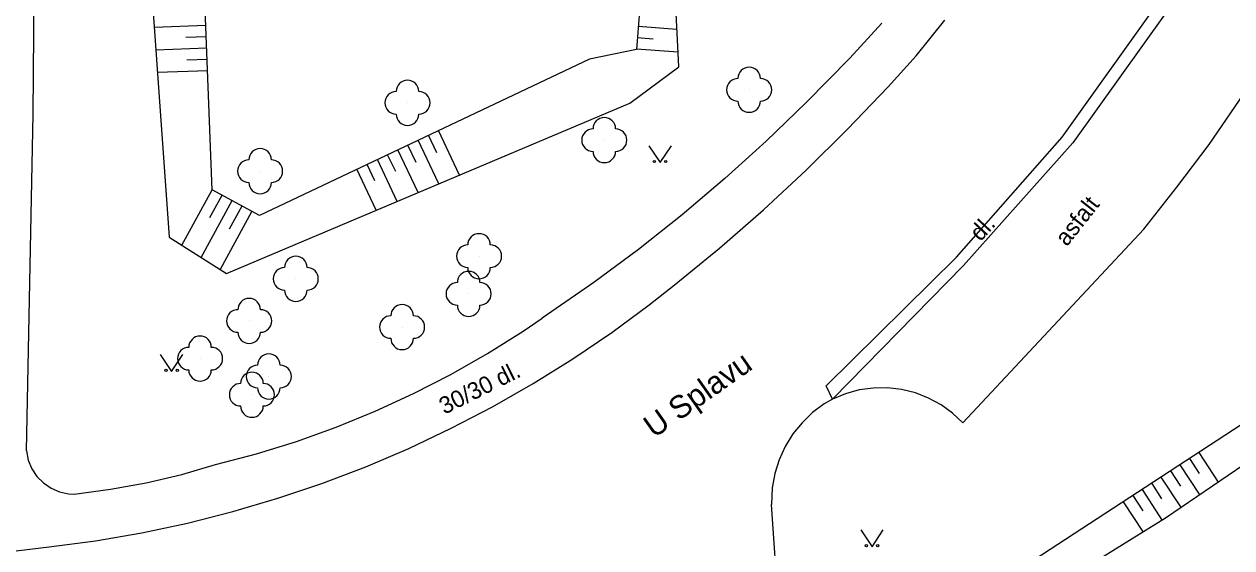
# Model space of a CAD drawing. Extents: x -584400 to -581602, y -1210894 to -1208793.
# Drawn here: x -583030.8 to -582977.3, y -1210509.9 to -1210486.7 of the extents above; entities that cross this region are included whole.
import ezdxf

# ---------------------------------------------------------------- set-up
doc = ezdxf.new("R2010")
doc.units = 0
for name, color, linetype in [('NÁZVY_ULIC_TOK_SMĚR', 7, 'Continuous'), ('POMOC_POPIS', 7, 'Continuous'), ('ROZHRANÍ_PLOCH', 7, 'Continuous'), ('VÝŠKOPIS', 7, 'Continuous'), ('ZELEŇ', 7, 'Continuous'), ('ZN_DOPLŇKOVÉ', 7, 'Continuous'), ('ZN_KULTUR', 7, 'Continuous')]:
    doc.layers.add(name, color=color, linetype=linetype)

msp = doc.modelspace()

# ---------------------------------------------------------------- linework, layer by layer
at = {"layer": 'ROZHRANÍ_PLOCH'}
for points in [[(-582994.96, -1210503.31), (-582995.24, -1210502.72), (-582989.47, -1210497.01), (-582984.79, -1210491.69), (-582980.68, -1210485.94), (-582976.77, -1210479.26), (-582974.08, -1210472.67), (-582971.69, -1210464.31), (-582970.39, -1210456.48), (-582969.87, -1210447.15), (-582969.4, -1210447.87)], [(-582969.4, -1210447.87), (-582969.86, -1210456.52), (-582971.17, -1210464.44), (-582973.64, -1210472.89), (-582976.31, -1210479.47), (-582980.23, -1210486.22), (-582984.31, -1210491.94), (-582989.16, -1210497.38), (-582994.96, -1210503.31)], [(-583030.67, -1210505.6), (-583030.37, -1210490.67), (-583030.19, -1210469.05), (-583024.56, -1210469.18)], [(-582989.19, -1210504.36), (-582981.17, -1210495.77), (-582979.7, -1210493.91), (-582978.28, -1210492.01), (-582976.93, -1210490.05), (-582975.65, -1210488.06), (-582974.43, -1210486.02), (-582973.28, -1210483.95), (-582972.21, -1210481.83), (-582971.2, -1210479.68), (-582970.27, -1210477.5), (-582969.42, -1210475.29), (-582968.42, -1210472.37)], [(-583032.48, -1210510.2), (-583029.66, -1210509.86), (-583027.61, -1210509.59), (-583025.56, -1210509.23), (-583023.54, -1210508.8), (-583021.53, -1210508.29), (-583019.54, -1210507.7), (-583017.58, -1210507.04), (-583015.64, -1210506.3), (-583013.73, -1210505.49), (-583011.86, -1210504.6), (-583010.02, -1210503.64), (-583008.22, -1210502.61), (-583006.46, -1210501.52), (-583004.74, -1210500.35), (-583003.08, -1210499.13), (-583001.98, -1210498.26), (-582999.97, -1210496.62), (-582998.02, -1210494.92), (-582996.13, -1210493.16), (-582994.29, -1210491.34), (-582992.5, -1210489.46), (-582991.26, -1210488.08), (-582989.98, -1210486.51)], [(-582992.77, -1210486.63), (-582994.2, -1210488.19), (-582996.13, -1210490.16), (-582997.9, -1210491.87), (-582999.73, -1210493.53), (-583001.62, -1210495.13), (-583003.55, -1210496.67), (-583005.53, -1210498.14), (-583007.82, -1210499.72)], [(-583030.67, -1210505.6), (-583030.59, -1210506.01), (-583030.43, -1210506.39), (-583030.21, -1210506.73), (-583029.92, -1210507.02), (-583029.58, -1210507.26), (-583029.2, -1210507.42), (-583028.8, -1210507.5), (-583028.55, -1210507.52), (-583026.95, -1210507.3), (-583025.36, -1210507.01), (-583023.79, -1210506.64), (-583022.29, -1210506.21), (-583020.48, -1210505.73), (-583018.7, -1210505.18), (-583016.95, -1210504.55), (-583015.22, -1210503.84), (-583013.53, -1210503.06), (-583011.87, -1210502.21), (-583010.25, -1210501.28), (-583008.67, -1210500.29), (-583007.82, -1210499.72)], [(-582989.19, -1210504.36), (-582989.64, -1210503.93), (-582990.15, -1210503.56), (-582990.71, -1210503.26), (-582991.29, -1210503.03), (-582991.9, -1210502.88), (-582992.53, -1210502.81), (-582993.15, -1210502.82), (-582993.78, -1210502.9), (-582994.38, -1210503.07), (-582994.96, -1210503.31), (-582995.33, -1210503.51), (-582995.85, -1210503.9), (-582996.31, -1210504.35), (-582996.72, -1210504.85), (-582997.06, -1210505.4), (-582997.32, -1210505.99), (-582997.52, -1210506.61), (-582997.63, -1210507.24), (-582997.67, -1210507.97)], [(-582997.36, -1210512.47), (-582997.67, -1210507.97)]]:
    msp.add_lwpolyline(points, dxfattribs=at)
at = {"layer": 'VÝŠKOPIS'}
for points in [[(-583024.56, -1210469.18), (-583025.47, -1210480.35), (-583024.34, -1210496.12), (-583021.8, -1210497.73), (-583003.94, -1210490.18), (-583001.77, -1210488.58), (-583001.94, -1210485)], [(-583003.43, -1210484.95), (-583003.65, -1210487.8), (-583005.72, -1210488.23), (-583020.35, -1210495.16), (-583022.44, -1210494.02), (-583022.97, -1210480.31), (-583022.68, -1210469.15)], [(-583025.01, -1210486.82), (-583022.72, -1210486.73)], [(-583023.61, -1210487.26), (-583022.7, -1210487.23)], [(-583002.9, -1210487.34), (-583003.61, -1210487.29)], [(-583001.85, -1210486.92), (-583003.57, -1210486.79)], [(-583024.94, -1210487.82), (-583022.68, -1210487.73)], [(-583001.8, -1210487.93), (-583003.65, -1210487.79)], [(-583023.56, -1210488.26), (-583022.66, -1210488.23)], [(-582953.14, -1210488.24), (-582968.74, -1210499.14), (-582989.57, -1210512.75), (-582989.98, -1210514.65), (-582996.03, -1210517.29)], [(-583024.86, -1210488.81), (-583022.64, -1210488.73)], [(-583011.48, -1210493.37), (-583012.41, -1210491.4)], [(-583013.4, -1210492.81), (-583013.77, -1210492.04)], [(-583012.4, -1210493.76), (-583013.31, -1210491.83)], [(-583012.49, -1210492.39), (-583012.86, -1210491.61)], [(-583014.31, -1210493.22), (-583014.67, -1210492.47)], [(-583013.32, -1210494.15), (-583014.22, -1210492.25)], [(-583015.17, -1210494.93), (-583016.03, -1210493.11)], [(-583015.23, -1210493.63), (-583015.57, -1210492.9)], [(-583014.24, -1210494.54), (-583015.12, -1210492.68)], [(-583023.78, -1210496.48), (-583022.44, -1210494.02)], [(-583022.54, -1210495.25), (-583022, -1210494.26)], [(-583022.93, -1210497.02), (-583021.56, -1210494.5)], [(-583021.67, -1210495.76), (-583021.12, -1210494.74)], [(-583022.08, -1210497.55), (-583020.68, -1210494.98)], [(-582979.15, -1210505.94), (-582978.72, -1210506.61)], [(-582978.73, -1210505.67), (-582977.87, -1210506.99)], [(-582979.99, -1210506.49), (-582979.55, -1210507.16)], [(-582979.57, -1210506.22), (-582978.69, -1210507.56)], [(-582980.82, -1210507.04), (-582980.38, -1210507.72)], [(-582980.41, -1210506.76), (-582979.52, -1210508.12)], [(-582981.66, -1210507.58), (-582981.22, -1210508.26)], [(-582981.24, -1210507.31), (-582980.35, -1210508.68)], [(-582982.08, -1210507.86), (-582981.2, -1210509.2)]]:
    msp.add_lwpolyline(points, dxfattribs=at)
at = {"layer": 'ZELEŇ'}
for centre in [(-582998.65, -1210489.59), (-583013.79, -1210490.17), (-583005.07, -1210491.82), (-583020.32, -1210493.2), (-583010.62, -1210496.97), (-583018.74, -1210497.97), (-583011.08, -1210498.64), (-583020.8, -1210499.84), (-583014.03, -1210500.11), (-583022.98, -1210501.51), (-583019.93, -1210502.3), (-583020.68, -1210503.11)]:
    msp.add_circle(centre, 0.0005, dxfattribs=at)
for centre, start, end in [((-582998.65, -1210489.09), 360, 180), ((-583013.79, -1210489.67), 360, 180), ((-582999.15, -1210489.59), 90, 270), ((-582998.15, -1210489.59), 270, 90), ((-583014.29, -1210490.17), 90, 270), ((-583013.29, -1210490.17), 270, 90), ((-582998.65, -1210490.09), 180, 360), ((-583013.79, -1210490.67), 180, 360), ((-583005.07, -1210491.32), 0, 180), ((-583005.57, -1210491.82), 90, 270), ((-583004.57, -1210491.82), 270, 90), ((-583020.32, -1210492.7), 360, 180), ((-583005.07, -1210492.32), 180, 360), ((-583020.82, -1210493.2), 90, 270), ((-583019.82, -1210493.2), 270, 90), ((-583020.32, -1210493.7), 180, 360), ((-583010.62, -1210496.47), 360, 180), ((-583011.12, -1210496.97), 90, 270), ((-583010.12, -1210496.97), 270, 90), ((-583019.24, -1210497.97), 90, 270), ((-583018.74, -1210497.47), 360, 180), ((-583018.24, -1210497.97), 270, 90), ((-583010.62, -1210497.47), 180, 360), ((-583011.08, -1210498.14), 360, 180), ((-583018.74, -1210498.47), 180, 360), ((-583011.58, -1210498.64), 90, 270), ((-583010.58, -1210498.64), 270, 90), ((-583020.8, -1210499.34), 360, 180), ((-583021.3, -1210499.84), 90, 270), ((-583020.3, -1210499.84), 270, 90), ((-583014.53, -1210500.11), 90, 270), ((-583014.03, -1210499.61), 360, 180), ((-583013.53, -1210500.11), 270, 90), ((-583011.08, -1210499.14), 180, 360), ((-583022.98, -1210501.01), 360, 180), ((-583020.8, -1210500.34), 180, 360), ((-583014.03, -1210500.61), 180, 360), ((-583023.48, -1210501.51), 90, 270), ((-583022.48, -1210501.51), 270, 90), ((-583019.93, -1210501.8), 360, 180), ((-583022.98, -1210502.01), 180, 360), ((-583020.68, -1210502.61), 360, 180), ((-583020.43, -1210502.3), 90, 270), ((-583019.43, -1210502.3), 270, 90), ((-583021.18, -1210503.11), 90, 270), ((-583019.93, -1210502.8), 180, 360), ((-583020.18, -1210503.11), 270, 90), ((-583020.68, -1210503.61), 180, 360)]:
    msp.add_arc(centre, 0.5, start, end, dxfattribs=at)
at = {"layer": 'ZN_DOPLŇKOVÉ'}
msp.add_lwpolyline([(-582934.54, -1210546.78), (-582930.27, -1210545.25), (-582936.45, -1210528.67), (-582949.03, -1210495.16), (-582951.76, -1210489.19), (-582980.21, -1210508.59), (-582988.06, -1210513.46), (-582987.34, -1210516.02)], dxfattribs=at)
at = {"layer": 'ZN_KULTUR'}
for points in [[(-583003.1, -1210492.07), (-583002.6, -1210492.82), (-583002.1, -1210492.07)], [(-583024.74, -1210501.33), (-583024.24, -1210502.08), (-583023.74, -1210501.33)], [(-582993.71, -1210509.1), (-582993.21, -1210509.85), (-582992.71, -1210509.1)]]:
    msp.add_lwpolyline(points, dxfattribs=at)
for centre in [(-583002.85, -1210492.77), (-583002.35, -1210492.77), (-583024.49, -1210502.03), (-583023.99, -1210502.03), (-582993.46, -1210509.8), (-582992.96, -1210509.8)]:
    msp.add_circle(centre, 0.05, dxfattribs=at)

# ---------------------------------------------------------------- texts
at = {"layer": 'NÁZVY_ULIC_TOK_SMĚR'}
msp.add_text('U Splavu', height=1, rotation=35.1207, dxfattribs=at).set_placement((-583002.87, -1210505.06))
at = {"layer": 'POMOC_POPIS'}
for s, rotation, p in [('asfalt', 51.6799, (-582984.58, -1210496.57)), ('dl.', 46.9583, (-582988.41, -1210496.35)), ('30/30 dl.', 26.5021, (-583012.15, -1210504))]:
    msp.add_text(s, height=0.75, rotation=rotation, dxfattribs=at).set_placement(p)

doc.saveas('drawing.dxf')
